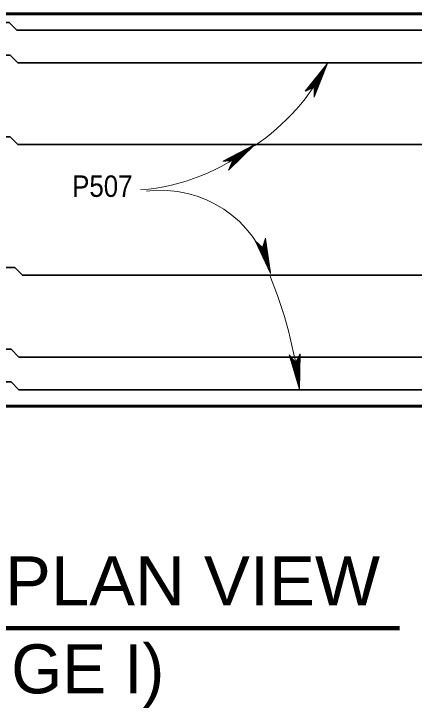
# Model space of a CAD drawing. Extents: x 144 to 252, y 360 to 425.
# Drawn here: x 168.83 to 174.95, y 407.25 to 417.87 of the extents above; entities that cross this region are included whole.
import ezdxf
from ezdxf.enums import TextEntityAlignment as Align

# ---------------------------------------------------------------- set-up
doc = ezdxf.new("R2010")
doc.units = 0
doc.header["$LTSCALE"] = 0.13
for name, color, linetype, lineweight in [('1', 7, 'Continuous', 40), ('14', 7, 'Continuous', 13), ('16', 7, 'Continuous', 13), ('3', 7, 'Continuous', 13)]:
    doc.layers.add(name, color=color, linetype=linetype, lineweight=lineweight)

msp = doc.modelspace()

# ---------------------------------------------------------------- linework, layer by layer
at = {"layer": '1', "lineweight": 35}
for p, q in [((168.8734, 417.6206), (180.5312, 417.6206)), ((168.8907, 417.1206), (180.5312, 417.1206)), ((168.8907, 415.8706), (180.5312, 415.8706)), ((168.9595, 413.8706), (180.5312, 413.8706)), ((168.9602, 413.8706), (180.5312, 413.8706)), ((168.9081, 412.6206), (180.5312, 412.6206)), ((168.9081, 412.1206), (180.5312, 412.1206))]:
    msp.add_line(p, q, dxfattribs=at)
at = {"layer": '1', "lineweight": 60}
msp.add_lwpolyline([(156.7812, 417.8706), (180.7812, 417.8706), (180.7812, 411.8706), (156.7812, 411.8706)], close=True, dxfattribs=at)
at = {"layer": '14', "lineweight": 106}
msp.add_line((163.2287, 408.4708), (174.7287, 408.4708), dxfattribs=at)
at = {"layer": '3'}
for p, q in [((173.6252, 417.111), (173.2821, 416.6875)), ((173.6175, 417.0988), (173.2858, 416.6892)), ((173.6121, 417.0893), (173.2893, 416.6908)), ((173.605, 417.0768), (173.2943, 416.693)), ((173.5987, 417.0657), (173.2984, 416.6949)), ((173.5931, 417.0559), (173.3022, 416.6966)), ((173.586, 417.0433), (173.307, 416.6987)), ((173.5797, 417.0322), (173.3113, 416.7007)), ((173.4201, 416.7498), (173.6252, 417.111)), ((173.4214, 416.6307), (173.5797, 417.0322)), ((173.4215, 416.626), (173.586, 417.0433)), ((173.4216, 416.6164), (173.5987, 417.0657)), ((173.4216, 416.6164), (173.5987, 417.0657)), ((173.4216, 416.6207), (173.5931, 417.0559)), ((173.4218, 416.5954), (173.6252, 417.111)), ((173.4218, 416.6023), (173.6175, 417.0988)), ((173.4218, 416.6064), (173.6121, 417.0893)), ((173.4218, 416.6117), (173.605, 417.0768)), ((173.5729, 417.0203), (173.3158, 416.7027)), ((173.5661, 417.0082), (173.3204, 416.7048)), ((173.5595, 416.9967), (173.3248, 416.7068)), ((173.5527, 416.9847), (173.3294, 416.7089)), ((173.5464, 416.9737), (173.3336, 416.7108)), ((173.5408, 416.9638), (173.3375, 416.7126)), ((173.5331, 416.9502), (173.3427, 416.7149)), ((173.5263, 416.9382), (173.3473, 416.717)), ((173.5169, 416.9228), (173.352, 416.7192)), ((173.4208, 416.6792), (173.5169, 416.9228)), ((173.4209, 416.6709), (173.5263, 416.9382)), ((173.421, 416.6755), (173.5175, 416.9206)), ((173.4211, 416.6601), (173.5408, 416.9638)), ((173.4211, 416.6658), (173.5331, 416.9502)), ((173.4212, 416.6458), (173.5595, 416.9967)), ((173.4212, 416.6511), (173.5527, 416.9847)), ((173.4212, 416.6557), (173.5464, 416.9737)), ((173.4213, 416.6409), (173.5661, 417.0082)), ((173.4214, 416.6358), (173.5729, 417.0203)), ((173.5101, 416.9106), (173.3567, 416.7213)), ((173.5036, 416.8992), (173.3611, 416.7233)), ((173.4995, 416.891), (173.3653, 416.7252)), ((173.4936, 416.8806), (173.3693, 416.727)), ((173.4868, 416.8686), (173.3739, 416.7291)), ((173.479, 416.8549), (173.3791, 416.7315)), ((173.4728, 416.844), (173.3833, 416.7333)), ((173.4663, 416.8325), (173.3877, 416.7353)), ((173.4603, 416.822), (173.3918, 416.7372)), ((173.4203, 416.7206), (173.4603, 416.822)), ((173.4204, 416.7161), (173.4663, 416.8325)), ((173.4205, 416.7112), (173.4728, 416.844)), ((173.4206, 416.7007), (173.4868, 416.8686)), ((173.4206, 416.7064), (173.479, 416.8549)), ((173.4207, 416.6892), (173.5036, 416.8992)), ((173.4207, 416.691), (173.4995, 416.891)), ((173.4207, 416.6955), (173.4936, 416.8806)), ((173.4208, 416.6843), (173.5101, 416.9106)), ((173.2821, 416.6875), (173.4201, 416.75)), ((173.4532, 416.8094), (173.3965, 416.7394)), ((173.4463, 416.7974), (173.4012, 416.7415)), ((173.4401, 416.7864), (173.4053, 416.7433)), ((173.4336, 416.7748), (173.4098, 416.7453)), ((173.4279, 416.7649), (173.4135, 416.7472)), ((173.4229, 416.7561), (173.4169, 416.7487)), ((173.4201, 416.7449), (173.4279, 416.7649)), ((173.4201, 416.75), (173.4218, 416.5954)), ((173.4202, 416.731), (173.4463, 416.7974)), ((173.4202, 416.7357), (173.4401, 416.7864)), ((173.4202, 416.7418), (173.4294, 416.7654)), ((173.4203, 416.7259), (173.4532, 416.8094)), ((172.5072, 415.8689), (172.0228, 415.6191)), ((172.4953, 415.8608), (172.0268, 415.6192)), ((172.1138, 415.4786), (172.5072, 415.8689)), ((172.1165, 415.4849), (172.4953, 415.8608)), ((172.1743, 415.6206), (172.5072, 415.8689)), ((172.4866, 415.8543), (172.0308, 415.6192)), ((172.4751, 415.8458), (172.0362, 415.6192)), ((172.4648, 415.8381), (172.0408, 415.6193)), ((172.4557, 415.8313), (172.0449, 415.6193)), ((172.4442, 415.8227), (172.0502, 415.6193)), ((172.434, 415.8151), (172.0548, 415.6194)), ((172.4229, 415.8069), (172.0598, 415.6195)), ((172.4118, 415.7986), (172.0649, 415.6196)), ((172.4013, 415.7907), (172.0697, 415.6196)), ((172.3901, 415.7824), (172.0748, 415.6197)), ((172.38, 415.7748), (172.0794, 415.6198)), ((172.3708, 415.768), (172.0837, 415.6198)), ((172.3582, 415.7587), (172.0893, 415.6198)), ((172.3472, 415.7504), (172.0944, 415.6199)), ((172.1182, 415.4887), (172.4866, 415.8543)), ((172.1202, 415.4935), (172.4751, 415.8458)), ((172.1221, 415.4979), (172.4648, 415.8381)), ((172.1221, 415.4979), (172.4648, 415.8381)), ((172.1237, 415.5018), (172.4557, 415.8313)), ((172.1257, 415.5068), (172.4442, 415.8227)), ((172.1276, 415.5111), (172.434, 415.8151)), ((172.1297, 415.5157), (172.4229, 415.8069)), ((172.1317, 415.5204), (172.4118, 415.7986)), ((172.1336, 415.525), (172.4013, 415.7907)), ((172.1356, 415.5298), (172.3901, 415.7824)), ((172.1374, 415.534), (172.38, 415.7748)), ((172.1391, 415.5381), (172.3708, 415.768)), ((172.1414, 415.5433), (172.3582, 415.7587)), ((172.1433, 415.5481), (172.3472, 415.7504)), ((172.3324, 415.74), (172.0997, 415.62)), ((172.3213, 415.7317), (172.1047, 415.6201)), ((172.3107, 415.7238), (172.1095, 415.6201)), ((172.3038, 415.718), (172.1142, 415.6201)), ((172.2942, 415.7108), (172.1186, 415.6202)), ((172.2831, 415.7026), (172.1237, 415.6202)), ((172.2705, 415.6932), (172.1293, 415.6204)), ((172.2604, 415.6857), (172.1339, 415.6204)), ((172.2498, 415.6778), (172.1387, 415.6205)), ((172.2402, 415.6706), (172.1432, 415.6205)), ((172.1453, 415.5523), (172.3322, 415.7378)), ((172.1466, 415.5557), (172.3324, 415.74)), ((172.2285, 415.6619), (172.1484, 415.6206)), ((172.1486, 415.5604), (172.3213, 415.7317)), ((172.1505, 415.565), (172.3107, 415.7238)), ((172.1513, 415.5666), (172.3038, 415.718)), ((172.153, 415.5707), (172.2942, 415.7108)), ((172.2174, 415.6537), (172.1536, 415.6207)), ((172.155, 415.5755), (172.2831, 415.7026)), ((172.1573, 415.5807), (172.2705, 415.6932)), ((172.2073, 415.6461), (172.1582, 415.6207)), ((172.1591, 415.5851), (172.2604, 415.6857)), ((172.161, 415.5897), (172.2498, 415.6778)), ((172.1627, 415.5938), (172.2402, 415.6706)), ((172.1649, 415.5987), (172.2285, 415.6619)), ((172.1669, 415.6034), (172.2174, 415.6537)), ((172.1687, 415.6077), (172.2073, 415.6461)), ((172.0228, 415.6191), (172.1743, 415.6209)), ((172.1743, 415.6209), (172.1138, 415.4786)), ((172.1967, 415.6382), (172.163, 415.6207)), ((172.1875, 415.6313), (172.1672, 415.6208)), ((172.1793, 415.6252), (172.1709, 415.6208)), ((172.1712, 415.6133), (172.1891, 415.6312)), ((172.1723, 415.6162), (172.1875, 415.6313)), ((172.5171, 414.3995), (172.7557, 413.8992)), ((172.6314, 414.2954), (172.5171, 414.3995)), ((172.5222, 414.3948), (172.752, 413.9132)), ((172.5252, 414.3921), (172.7488, 413.9235)), ((172.5291, 414.3885), (172.7444, 413.9373)), ((172.5326, 414.3853), (172.7406, 413.9494)), ((172.5326, 414.3853), (172.7406, 413.9494)), ((172.5358, 414.3825), (172.7372, 413.9602)), ((172.5397, 414.3789), (172.7329, 413.974)), ((172.5433, 414.3757), (172.7291, 413.9862)), ((172.5469, 414.3723), (172.7249, 413.9993)), ((172.5507, 414.3688), (172.7208, 414.0125)), ((172.6797, 414.4389), (172.6314, 414.2954)), ((172.6967, 414.0895), (172.6569, 414.3712)), ((172.7007, 414.0762), (172.6585, 414.376)), ((172.7055, 414.0613), (172.6603, 414.3813)), ((172.7089, 414.0504), (172.6617, 414.3853)), ((172.7127, 414.0384), (172.6632, 414.3897)), ((172.7168, 414.0252), (172.6647, 414.3945)), ((172.7208, 414.0125), (172.6663, 414.3991)), ((172.7249, 413.9993), (172.6679, 414.4039)), ((172.7291, 413.9862), (172.6695, 414.4087)), ((172.7329, 413.974), (172.671, 414.4131)), ((172.7372, 413.9602), (172.6728, 414.4181)), ((172.7406, 413.9494), (172.6741, 414.422)), ((172.7444, 413.9373), (172.6755, 414.4263)), ((172.7488, 413.9235), (172.6772, 414.4313)), ((172.752, 413.9132), (172.6785, 414.4352)), ((172.7557, 413.8992), (172.6797, 414.4389)), ((172.5544, 414.3655), (172.7168, 414.0252)), ((172.5582, 414.362), (172.7127, 414.0384)), ((172.5616, 414.3589), (172.7089, 414.0504)), ((172.5649, 414.356), (172.7055, 414.0613)), ((172.5691, 414.3521), (172.7007, 414.0762)), ((172.5729, 414.3487), (172.6967, 414.0895)), ((172.5763, 414.3455), (172.6898, 414.1078)), ((172.5791, 414.3431), (172.6917, 414.1067)), ((172.5828, 414.3396), (172.6876, 414.1201)), ((172.5865, 414.3363), (172.6836, 414.1327)), ((172.5877, 414.3352), (172.6804, 414.1412)), ((172.5911, 414.3321), (172.6768, 414.1526)), ((172.5949, 414.3287), (172.6727, 414.1658)), ((172.5992, 414.3247), (172.668, 414.1807)), ((172.6027, 414.3216), (172.6642, 414.1927)), ((172.6063, 414.3182), (172.6602, 414.2054)), ((172.6097, 414.3152), (172.6567, 414.2168)), ((172.6136, 414.3116), (172.6522, 414.2307)), ((172.6173, 414.3082), (172.6482, 414.2438)), ((172.6208, 414.305), (172.6443, 414.2559)), ((172.6253, 414.3009), (172.6362, 414.2781)), ((172.6277, 414.2988), (172.6369, 414.2795)), ((172.6312, 414.2956), (172.7557, 413.8992)), ((172.6339, 414.2892), (172.6325, 414.2986)), ((172.6369, 414.2795), (172.6337, 414.3022)), ((172.6403, 414.2686), (172.6351, 414.3062)), ((172.6443, 414.2559), (172.6366, 414.3107)), ((172.6482, 414.2438), (172.6381, 414.3151)), ((172.6522, 414.2307), (172.6397, 414.3199)), ((172.6567, 414.2168), (172.6413, 414.3248)), ((172.6602, 414.2054), (172.6428, 414.3291)), ((172.6642, 414.1927), (172.6443, 414.3337)), ((172.668, 414.1807), (172.6458, 414.338)), ((172.6727, 414.1658), (172.6475, 414.3434)), ((172.6768, 414.1526), (172.6492, 414.3483)), ((172.6804, 414.1412), (172.6506, 414.3524)), ((172.6836, 414.1327), (172.6521, 414.3568)), ((172.6876, 414.1201), (172.6536, 414.3613)), ((172.6917, 414.1067), (172.6552, 414.3662)), ((173.2061, 412.6697), (173.1366, 412.5352)), ((173.1993, 412.1248), (173.2061, 412.6697)), ((173.0393, 412.6554), (173.1993, 412.1248)), ((173.1366, 412.5352), (173.0393, 412.6554)), ((173.0437, 412.65), (173.1977, 412.1391)), ((173.0462, 412.6468), (173.1961, 412.1498)), ((173.0495, 412.6427), (173.1939, 412.1641)), ((173.0525, 412.6391), (173.192, 412.1767)), ((173.0525, 412.6391), (173.192, 412.1767)), ((173.0553, 412.6357), (173.1902, 412.1878)), ((173.0586, 412.6316), (173.1881, 412.2021)), ((173.0616, 412.6279), (173.1862, 412.2147)), ((173.0647, 412.624), (173.1841, 412.2283)), ((173.0679, 412.62), (173.182, 412.242)), ((173.071, 412.6162), (173.18, 412.2551)), ((173.0743, 412.6121), (173.1778, 412.2688)), ((173.0772, 412.6085), (173.1759, 412.2812)), ((173.08, 412.6052), (173.1743, 412.2926)), ((173.0835, 412.6007), (173.1718, 412.3081)), ((173.0868, 412.5967), (173.1697, 412.3218)), ((173.0897, 412.5931), (173.1658, 412.3409)), ((173.092, 412.5902), (173.1675, 412.3396)), ((173.0952, 412.5863), (173.1654, 412.3533)), ((173.0983, 412.5824), (173.1634, 412.3663)), ((173.0994, 412.5811), (173.1616, 412.3752)), ((173.1022, 412.5775), (173.1598, 412.3871)), ((173.1055, 412.5736), (173.1577, 412.4008)), ((173.1091, 412.5691), (173.1552, 412.4162)), ((173.1121, 412.5654), (173.1533, 412.4287)), ((173.1495, 412.4537), (173.1507, 412.5628)), ((173.1513, 412.4418), (173.1528, 412.5668)), ((173.1533, 412.4287), (173.1551, 412.571)), ((173.1552, 412.4162), (173.1573, 412.5751)), ((173.1577, 412.4008), (173.1598, 412.5802)), ((173.1598, 412.3871), (173.1621, 412.5847)), ((173.1616, 412.3752), (173.1641, 412.5886)), ((173.1634, 412.3663), (173.1662, 412.5927)), ((173.1654, 412.3533), (173.1685, 412.5969)), ((173.1675, 412.3396), (173.1708, 412.6015)), ((173.1697, 412.3218), (173.1732, 412.6062)), ((173.1718, 412.3081), (173.1756, 412.6107)), ((173.1743, 412.2926), (173.1782, 412.6157)), ((173.1759, 412.2812), (173.1801, 412.6195)), ((173.1778, 412.2688), (173.1822, 412.6236)), ((173.18, 412.2551), (173.1845, 412.6281)), ((173.182, 412.242), (173.1867, 412.6324)), ((173.1841, 412.2283), (173.1891, 412.6368)), ((173.1862, 412.2147), (173.1913, 412.6413)), ((173.1881, 412.2021), (173.1935, 412.6455)), ((173.1902, 412.1878), (173.196, 412.6502)), ((173.192, 412.1767), (173.1978, 412.6538)), ((173.1939, 412.1641), (173.1999, 412.6579)), ((173.1961, 412.1498), (173.2024, 412.6626)), ((173.1977, 412.1391), (173.2043, 412.6662)), ((173.1153, 412.5616), (173.1513, 412.4418)), ((173.118, 412.5581), (173.1495, 412.4537)), ((173.1213, 412.5539), (173.1473, 412.468)), ((173.1246, 412.5499), (173.1453, 412.4817)), ((173.1275, 412.5462), (173.1433, 412.4942)), ((173.1313, 412.5415), (173.1387, 412.5172)), ((173.1333, 412.5392), (173.1396, 412.5186)), ((173.1363, 412.5354), (173.1993, 412.1248)), ((173.1381, 412.5287), (173.1381, 412.5382)), ((173.1396, 412.5186), (173.1399, 412.5415)), ((173.1413, 412.5073), (173.1418, 412.5453)), ((173.1433, 412.4942), (173.144, 412.5495)), ((173.1453, 412.4817), (173.1461, 412.5536)), ((173.1473, 412.468), (173.1484, 412.5582))]:
    msp.add_line(p, q, dxfattribs=at)
at = {"layer": '3', "lineweight": 35}
for points in [[(168.8734, 417.6206), (168.7556, 417.7384), (167.7556, 417.7384)], [(168.8907, 417.1206), (168.7729, 417.2384), (167.7729, 417.2384)], [(168.8907, 415.8706), (168.7729, 415.9884), (167.7729, 415.9884)], [(168.9602, 413.8706), (168.8423, 413.9884), (167.8423, 413.9884)], [(168.9081, 412.6206), (168.7902, 412.7384), (167.7902, 412.7384)], [(168.9081, 412.1206), (168.7902, 412.2384), (167.7902, 412.2384)]]:
    msp.add_lwpolyline(points, dxfattribs=at)
at = {"layer": '3'}
for centre, radius, start, end in [((170.6474, 418.6274), 3.3416, 303.81849, 333.01283), ((170.5127, 418.3498), 3.1832, 274.60447, 308.79844), ((171.0749, 413.4268), 1.7459, 15.70016, 97.16844), ((166.5747, 411.324), 6.6728, 6.89185, 22.53614)]:
    msp.add_arc(centre, radius, start, end, dxfattribs=at)

# ---------------------------------------------------------------- texts
at = {"layer": '14', "width": 1.05}
msp.add_text('FOOTING PLAN VIEW', height=0.75, dxfattribs=at).set_placement((169.0155, 408.8194), align=Align.CENTER)
at = {"layer": '14'}
msp.add_text('(RANGE I)', height=0.75, dxfattribs=at).set_placement((168.7339, 407.4742), align=Align.CENTER)
at = {"layer": '16', "width": 0.9}
msp.add_text('P507', height=0.3281, dxfattribs=at).set_placement((170.1827, 415.0706), align=Align.CENTER)

doc.saveas('drawing.dxf')
